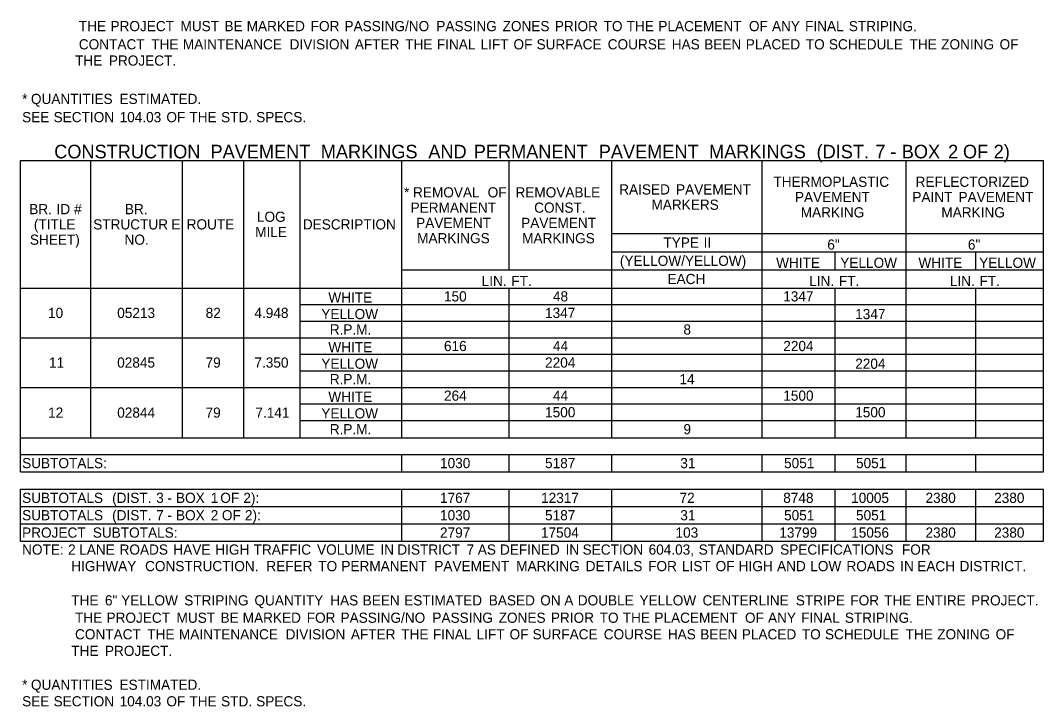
# Model space of a CAD drawing. Extents: x 544478 to 1930787, y -1948294 to 596640.
# Drawn here: x 557631 to 558234, y -1946952 to -1946548 of the extents above; entities that cross this region are included whole.
import ezdxf

# ---------------------------------------------------------------- set-up
doc = ezdxf.new("R2010")
doc.units = 0
doc.layers.add('Default', color=7, linetype='Continuous')

msp = doc.modelspace()

# ---------------------------------------------------------------- linework, layer by layer
at = {"layer": 'Default'}
for p, q in [((557631.45, -1946630.7), (558234.48, -1946630.7)), ((557631.45, -1946630.7), (557856.18, -1946630.7)), ((557631.45, -1946814), (557631.45, -1946630.7)), ((557672.88, -1946794.01), (557672.88, -1946630.7)), ((557727, -1946794.01), (557727, -1946630.7)), ((557763.07, -1946794.01), (557763.07, -1946630.7)), ((557796.22, -1946794.01), (557796.22, -1946630.7)), ((557856.18, -1946794.01), (557856.18, -1946630.7)), ((557919.56, -1946630.7), (557980.01, -1946630.7)), ((557919.56, -1946695.05), (557919.56, -1946630.7)), ((557980.01, -1946794.01), (557980.01, -1946630.7)), ((558068.73, -1946794.01), (558068.73, -1946630.7)), ((558153.56, -1946705.77), (558153.56, -1946630.7)), ((558153.56, -1946794.01), (558153.56, -1946630.7)), ((558234.48, -1946814), (558234.48, -1946630.7)), ((557980.01, -1946673.6), (558234.48, -1946673.6)), ((557980.01, -1946684.32), (558234.48, -1946684.32)), ((558111.63, -1946695.05), (558111.63, -1946684.32)), ((558194.51, -1946695.05), (558194.51, -1946684.32)), ((557856.18, -1946695.05), (558234.48, -1946695.05)), ((558068.73, -1946725.27), (558068.73, -1946695.05)), ((557631.45, -1946705.77), (557856.18, -1946705.77)), ((557631.45, -1946705.77), (557796.22, -1946705.77)), ((557796.22, -1946705.77), (558234.48, -1946705.77)), ((557919.56, -1946725.27), (557919.56, -1946705.77)), ((557919.56, -1946794.01), (557919.56, -1946705.77)), ((558111.63, -1946794.01), (558111.63, -1946705.77)), ((558111.63, -1946794.01), (558111.63, -1946705.77)), ((558194.51, -1946794.01), (558194.51, -1946705.77)), ((558194.51, -1946794.01), (558194.51, -1946705.77)), ((557796.22, -1946715.52), (558234.48, -1946715.52)), ((557796.22, -1946794.01), (557796.22, -1946715.52)), ((557856.18, -1946725.27), (557856.18, -1946715.52)), ((557796.22, -1946725.27), (558234.48, -1946725.27)), ((557631.45, -1946735.02), (558234.48, -1946735.02)), ((557796.22, -1946735.02), (557856.18, -1946735.02)), ((557856.18, -1946754.52), (557856.18, -1946735.02)), ((557919.56, -1946754.52), (557919.56, -1946735.02)), ((558068.73, -1946754.52), (558068.73, -1946735.02)), ((557796.22, -1946744.77), (558234.48, -1946744.77)), ((557796.22, -1946754.52), (558234.48, -1946754.52)), ((557631.45, -1946764.27), (558234.48, -1946764.27)), ((557856.18, -1946783.77), (557856.18, -1946764.27)), ((557919.56, -1946783.77), (557919.56, -1946764.27)), ((558068.73, -1946794.01), (558068.73, -1946764.27)), ((557796.22, -1946774.02), (558234.48, -1946774.02)), ((557796.22, -1946783.77), (558234.48, -1946783.77)), ((557631.45, -1946794.01), (558234.48, -1946794.01)), ((557919.56, -1946794.01), (557980.01, -1946794.01)), ((557980.01, -1946794.01), (558234.48, -1946794.01)), ((557631.45, -1946803.76), (558068.73, -1946803.76)), ((557631.45, -1946803.76), (557980.01, -1946803.76)), ((557856.18, -1946814), (557856.18, -1946803.76)), ((557856.18, -1946814), (557856.18, -1946803.76)), ((557919.56, -1946814), (557919.56, -1946803.76)), ((557919.56, -1946814), (557919.56, -1946803.76)), ((557980.01, -1946803.76), (558234.48, -1946803.76)), ((557980.01, -1946814), (557980.01, -1946803.76)), ((557980.01, -1946814), (557980.01, -1946803.76)), ((558068.73, -1946814), (558068.73, -1946803.76)), ((558068.73, -1946814), (558068.73, -1946803.76)), ((558111.63, -1946803.76), (558234.48, -1946803.76)), ((558111.63, -1946814), (558111.63, -1946803.76)), ((558111.63, -1946814), (558111.63, -1946803.76)), ((558153.56, -1946814), (558153.56, -1946803.76)), ((558153.56, -1946814), (558153.56, -1946803.76)), ((558194.51, -1946814), (558194.51, -1946803.76)), ((558194.51, -1946814), (558194.51, -1946803.76)), ((557631.45, -1946814), (558234.48, -1946814)), ((557631.45, -1946824.24), (558234.48, -1946824.24)), ((557631.45, -1946824.24), (558234.48, -1946824.24)), ((557631.45, -1946854.95), (557631.45, -1946824.24)), ((557856.18, -1946854.95), (557856.18, -1946824.24)), ((557856.18, -1946854.95), (557856.18, -1946824.24)), ((557919.56, -1946854.95), (557919.56, -1946824.24)), ((557919.56, -1946854.95), (557919.56, -1946824.24)), ((557980.01, -1946854.95), (557980.01, -1946824.24)), ((557980.01, -1946854.95), (557980.01, -1946824.24)), ((558068.73, -1946854.95), (558068.73, -1946824.24)), ((558068.73, -1946854.95), (558068.73, -1946824.24)), ((558111.63, -1946854.95), (558111.63, -1946824.24)), ((558111.63, -1946854.95), (558111.63, -1946824.24)), ((558153.56, -1946854.95), (558153.56, -1946824.24)), ((558153.56, -1946854.95), (558153.56, -1946824.24)), ((558194.51, -1946854.95), (558194.51, -1946824.24)), ((558194.51, -1946854.95), (558194.51, -1946824.24)), ((558234.48, -1946854.95), (558234.48, -1946824.24)), ((557631.45, -1946834.47), (558234.48, -1946834.47)), ((557631.45, -1946844.71), (558234.48, -1946844.71)), ((557631.45, -1946854.95), (558234.48, -1946854.95))]:
    msp.add_line(p, q, dxfattribs=at)

# ---------------------------------------------------------------- texts
for s, height, p in [(' THE', 6, (557663.62, -1946554.42)), (' PROJECT', 6, (557682.27, -1946554.42)), (' MUST', 6, (557723.56, -1946554.42)), (' BE', 6, (557749.47, -1946554.42)), (' MARKED', 6, (557762.54, -1946554.42)), (' FOR', 6, (557800.29, -1946554.42)), (' PASSING/NO', 6, (557820.2, -1946554.42)), (' PASSING', 6, (557874.34, -1946554.42)), (' ZONES', 6, (557913.41, -1946554.42)), (' PRIOR', 6, (557944.19, -1946554.42)), (' TO', 6, (557972.95, -1946554.42)), (' THE', 6, (557986.55, -1946554.42)), (' PLACEMENT', 6, (558005.2, -1946554.42)), (' OF', 6, (558058.6, -1946554.42)), (' ANY', 6, (558072.19, -1946554.42)), (' FINAL', 6, (558091.69, -1946554.42)), (' STRIPING.', 6, (558117.48, -1946554.42)), (' CONTACT', 6, (557663.62, -1946565.15)), (' THE', 6, (557706.3, -1946565.15)), (' MAINTENANCE', 6, (557724.95, -1946565.15)), (' DIVISION', 6, (557787.86, -1946565.15)), (' AFTER', 6, (557826.3, -1946565.15)), (' THE', 6, (557856, -1946565.15)), (' FINAL', 6, (557874.65, -1946565.15)), (' LIFT', 6, (557900.43, -1946565.15)), (' OF', 6, (557919.82, -1946565.15)), (' SURFACE', 6, (557933.41, -1946565.15)), (' COURSE', 6, (557975.36, -1946565.15)), (' HAS', 6, (558013.11, -1946565.15)), (' BEEN', 6, (558032.24, -1946565.15)), (' PLACED', 6, (558056.71, -1946565.15)), (' TO', 6, (558092.14, -1946565.15)), (' SCHEDULE', 6, (558105.74, -1946565.15)), (' THE', 6, (558153.28, -1946565.15)), (' ZONING', 6, (558171.93, -1946565.15)), (' OF', 6, (558206.33, -1946565.15)), ('              THE', 6, (557632.42, -1946574.71)), (' PROJECT.', 6, (557681.33, -1946574.71)), ('*', 6, (557632.42, -1946597.32)), (' QUANTITIES', 6, (557635.39, -1946597.32)), (' ESTIMATED.', 6, (557687.59, -1946597.32)), ('SEE', 6, (557632.42, -1946608.05)), (' SECTION', 6, (557648.75, -1946608.05)), (' 104.03', 6, (557687.66, -1946608.05)), (' OF', 6, (557715.24, -1946608.05)), (' THE', 6, (557728.82, -1946608.05)), (' STD.', 6, (557747.47, -1946608.05)), (' SPECS.', 6, (557768.17, -1946608.05)), ('CONSTRUCTION', 8, (557651.35, -1946629.34)), (' PAVEMENT', 8, (557740.5, -1946629.34)), (' MARKINGS', 8, (557805.49, -1946629.34)), (' AND', 8, (557868.9, -1946629.34)), (' PERMANENT', 8, (557895.67, -1946629.34)), (' PAVEMENT', 8, (557969.35, -1946629.34)), (' MARKINGS', 8, (558034.34, -1946629.34)), (' (DIST.', 8, (558097.75, -1946629.34)), (' 7', 8, (558132.37, -1946629.34)), (' BOX', 8, (558147.94, -1946629.34)), (' 2', 8, (558175.26, -1946629.34)), (' OF', 8, (558184.01, -1946629.34)), (' 2)', 8, (558202.12, -1946629.34)), (' -', 8, (558141.2, -1946629.34)), ('THERMOPLASTIC', 6, (558075.26, -1946646.15)), ('REFLECTORIZED', 6, (558159.06, -1946646.15)), ('*', 6, (557857.54, -1946652.37)), (' REMOVAL', 6, (557860.62, -1946652.37)), (' OF', 6, (557904.62, -1946652.37)), ('REMOVABLE', 6, (557923.21, -1946652.37)), ('RAISED', 6, (557984.37, -1946650.65)), (' PAVEMENT', 6, (558015.63, -1946650.65)), ('PAVEMENT', 6, (558087.94, -1946655.15)), ('PAINT', 6, (558157.16, -1946655.15)), (' PAVEMENT', 6, (558182.14, -1946655.15)), ('BR.', 6, (557636.64, -1946662.24)), (' ID', 6, (557650.5, -1946662.24)), (' #', 6, (557660.8, -1946662.24)), ('BR.', 6, (557693.01, -1946662.24)), ('PERMANENT', 6, (557861.41, -1946661.37)), ('CONST.', 6, (557934.24, -1946661.37)), ('MARKERS', 6, (558003.38, -1946659.65)), ('MARKING', 6, (558091.37, -1946664.15)), ('MARKING', 6, (558174.25, -1946664.15)), ('(TITLE', 6, (557639.34, -1946671.24)), ('STRUCTUR', 6, (557674.32, -1946671.24)), ('E', 6, (557720.39, -1946671.24)), ('ROUTE', 6, (557729.41, -1946671.24)), ('LOG', 6, (557770.82, -1946666.74)), ('DESCRIPTION', 6, (557797.89, -1946671.24)), ('PAVEMENT', 6, (557864.67, -1946670.37)), ('PAVEMENT', 6, (557926.58, -1946670.37)), ('MILE', 6, (557769.84, -1946675.74)), ('SHEET)', 6, (557637.01, -1946680.24)), ('NO.', 6, (557692.78, -1946680.24)), ('MARKINGS', 6, (557865.26, -1946679.37)), ('MARKINGS', 6, (557927.17, -1946679.37)), ('TYPE', 6, (558010.41, -1946681.96)), (' II', 6, (558031.89, -1946681.96)), ('6"', 6, (558107.04, -1946683.12)), ('6"', 6, (558189.91, -1946683.12)), ('(YELLOW/YELLOW)', 6, (557984.77, -1946692.69)), ('WHITE', 6, (558076.89, -1946693.85)), ('YELLOW', 6, (558114.67, -1946693.85)), ('WHITE', 6, (558160.74, -1946693.85)), ('YELLOW', 6, (558196.57, -1946693.85)), ('LIN.', 6, (557903.31, -1946704.57)), (' FT.', 6, (557918.56, -1946704.57)), ('EACH', 6, (558012.82, -1946703.41)), ('LIN.', 6, (558096.36, -1946704.57)), (' FT.', 6, (558111.61, -1946704.57)), ('LIN.', 6, (558179.23, -1946704.57)), (' FT.', 6, (558194.49, -1946704.57)), ('150', 6, (557881.08, -1946713.65)), ('48', 6, (557945.31, -1946713.65)), ('1347', 6, (558081.05, -1946713.65)), ('WHITE', 6, (557812.92, -1946714.32)), ('10', 6, (557647.71, -1946723.4)), ('05213', 6, (557688.48, -1946723.4)), ('82', 6, (557740.6, -1946723.4)), ('4.948', 6, (557769.35, -1946723.4)), ('YELLOW', 6, (557808.78, -1946724.07)), ('1347', 6, (557940.65, -1946723.4)), ('1347', 6, (558123.47, -1946724.07)), ('R.P.M.', 6, (557813.76, -1946733.15)), ('8', 6, (558022.23, -1946733.15)), ('WHITE', 6, (557812.92, -1946743.57)), ('616', 6, (557881.07, -1946742.9)), ('44', 6, (557945.33, -1946742.9)), ('2204', 6, (558081.07, -1946742.9)), ('11', 6, (557648.28, -1946752.65)), ('02845', 6, (557688.46, -1946752.65)), ('79', 6, (557740.56, -1946752.65)), ('7.350', 6, (557769.36, -1946752.65)), ('YELLOW', 6, (557808.78, -1946753.32)), ('2204', 6, (557940.67, -1946752.65)), ('2204', 6, (558123.48, -1946753.32)), ('R.P.M.', 6, (557813.76, -1946762.4)), ('14', 6, (558019.92, -1946762.4)), ('WHITE', 6, (557812.92, -1946772.82)), ('264', 6, (557881.09, -1946772.15)), ('44', 6, (557945.33, -1946772.15)), ('1500', 6, (558081.07, -1946772.15)), ('12', 6, (557647.73, -1946782.14)), ('02844', 6, (557688.49, -1946782.14)), ('79', 6, (557740.56, -1946782.14)), ('7.141', 6, (557769.93, -1946782.14)), ('YELLOW', 6, (557808.78, -1946782.57)), ('1500', 6, (557940.67, -1946781.9)), ('1500', 6, (558123.48, -1946781.9)), ('R.P.M.', 6, (557813.76, -1946791.89)), ('9', 6, (558022.23, -1946791.89)), ('SUBTOTALS:', 6, (557632.42, -1946811.88)), ('1030', 6, (557878.76, -1946811.88)), ('5187', 6, (557940.65, -1946811.88)), ('31', 6, (558020.39, -1946811.88)), ('5051', 6, (558081.54, -1946811.88)), ('5051', 6, (558123.96, -1946811.88)), ('SUBTOTALS', 6, (557632.42, -1946832.36)), (' (DIST.', 6, (557683.25, -1946832.36)), (' 3', 6, (557709.21, -1946832.36)), (' BOX', 6, (557720.9, -1946832.36)), (' 1', 6, (557741.39, -1946832.36)), (' OF', 6, (557747.02, -1946832.36)), (' 2):', 6, (557760.6, -1946832.36)), ('1767', 6, (557878.74, -1946832.36)), ('12317', 6, (557938.32, -1946832.36)), ('72', 6, (558019.92, -1946832.36)), ('8748', 6, (558081.05, -1946832.36)), ('10005', 6, (558121.07, -1946832.36)), ('2380', 6, (558164.92, -1946832.36)), ('2380', 6, (558205.38, -1946832.36)), (' -', 6, (557715.84, -1946832.36)), ('SUBTOTALS', 6, (557632.42, -1946842.59)), (' (DIST.', 6, (557683.25, -1946842.59)), (' 7', 6, (557709.21, -1946842.59)), (' -', 6, (557715.83, -1946842.59)), (' BOX', 6, (557720.89, -1946842.59)), (' 2', 6, (557741.38, -1946842.59)), (' OF', 6, (557747.94, -1946842.59)), (' 2):', 6, (557761.53, -1946842.59)), ('1030', 6, (557878.76, -1946842.59)), ('5187', 6, (557940.65, -1946842.59)), ('31', 6, (558020.39, -1946842.59)), ('5051', 6, (558081.54, -1946842.59)), ('5051', 6, (558123.96, -1946842.59)), ('PROJECT', 6, (557632.42, -1946852.83)), (' SUBTOTALS:', 6, (557671.85, -1946852.83)), ('2797', 6, (557878.74, -1946852.83)), ('17504', 6, (557938.23, -1946852.83)), ('103', 6, (558017.56, -1946852.83)), ('13799', 6, (558078.73, -1946852.83)), ('15056', 6, (558121.1, -1946852.83)), ('2380', 6, (558164.92, -1946852.83)), ('2380', 6, (558205.38, -1946852.83)), ('NOTE:', 6, (557632.42, -1946862.82)), (' 2', 6, (557657.31, -1946862.82)), (' LANE', 6, (557663.85, -1946862.82)), (' ROADS', 6, (557687.63, -1946862.82)), (' HAVE', 6, (557719.34, -1946862.82)), (' HIGH', 6, (557744.05, -1946862.82)), (' TRAFFIC', 6, (557766.66, -1946862.82)), (' VOLUME', 6, (557804.05, -1946862.82)), (' IN', 6, (557841.34, -1946862.82)), (' DISTRICT', 6, (557851.36, -1946862.82)), (' 7', 6, (557892.18, -1946862.82)), (' AS', 6, (557898.79, -1946862.82)), (' DEFINED', 6, (557911.86, -1946862.82)), (' IN', 6, (557950.54, -1946862.82)), (' SECTION', 6, (557960.57, -1946862.82)), (' 604.03,', 6, (557999.47, -1946862.82)), (' STANDARD', 6, (558029.01, -1946862.82)), (' SPECIFICATIONS', 6, (558077.01, -1946862.82)), (' FOR', 6, (558148.78, -1946862.82)), ('             HIGHWAY', 6, (557632.42, -1946872.57)), (' CONSTRUCTION.', 6, (557702.67, -1946872.57)), (' REFER', 6, (557774.14, -1946872.57)), (' TO', 6, (557804.77, -1946872.57)), (' PERMANENT', 6, (557818.36, -1946872.57)), (' PAVEMENT', 6, (557873.16, -1946872.57)), (' MARKING', 6, (557921.45, -1946872.57)), (' DETAILS', 6, (557962.38, -1946872.57)), (' FOR', 6, (557999.21, -1946872.57)), (' LIST', 6, (558019.12, -1946872.57)), (' OF', 6, (558038.98, -1946872.57)), (' HIGH', 6, (558052.57, -1946872.57)), (' AND', 6, (558075.18, -1946872.57)), (' LOW', 6, (558094.76, -1946872.57)), (' ROADS', 6, (558116.08, -1946872.57)), (' IN', 6, (558147.79, -1946872.57)), (' EACH', 6, (558157.82, -1946872.57)), (' DISTRICT.', 6, (558182.76, -1946872.57)), ('             THE', 6, (557632.42, -1946892.75)), (' 6"', 6, (557679, -1946892.75)), (' YELLOW', 6, (557688.58, -1946892.75)), (' STRIPING', 6, (557725.75, -1946892.75)), (' QUANTITY', 6, (557767.14, -1946892.75)), (' HAS', 6, (557811.8, -1946892.75)), (' BEEN', 6, (557830.92, -1946892.75)), (' ESTIMATED', 6, (557855.4, -1946892.75)), (' BASED', 6, (557905.26, -1946892.75)), (' ON', 6, (557935.57, -1946892.75)), (' A', 6, (557949.79, -1946892.75)), (' DOUBLE', 6, (557957.72, -1946892.75)), (' YELLOW', 6, (557994.08, -1946892.75)), (' CENTERLINE', 6, (558031.25, -1946892.75)), (' STRIPE', 6, (558086.24, -1946892.75)), (' FOR', 6, (558118.4, -1946892.75)), (' THE', 6, (558138.31, -1946892.75)), (' ENTIRE', 6, (558156.96, -1946892.75)), (' PROJECT.', 6, (558189.58, -1946892.75)), ('THE', 6, (557663.62, -1946902.99)), (' PROJECT', 6, (557679.94, -1946902.99)), (' MUST', 6, (557721.23, -1946902.99)), (' BE', 6, (557747.15, -1946902.99)), (' MARKED', 6, (557760.21, -1946902.99)), (' FOR', 6, (557797.96, -1946902.99)), (' PASSING/NO', 6, (557817.87, -1946902.99)), (' PASSING', 6, (557872.01, -1946902.99)), (' ZONES', 6, (557911.09, -1946902.99)), (' PRIOR', 6, (557941.86, -1946902.99)), (' TO', 6, (557970.62, -1946902.99)), (' THE', 6, (557984.22, -1946902.99)), (' PLACEMENT', 6, (558002.87, -1946902.99)), (' OF', 6, (558056.27, -1946902.99)), (' ANY', 6, (558069.86, -1946902.99)), (' FINAL', 6, (558089.37, -1946902.99)), (' STRIPING.', 6, (558115.15, -1946902.99)), ('CONTACT', 6, (557663.62, -1946912.74)), (' THE', 6, (557703.98, -1946912.74)), (' MAINTENANCE', 6, (557722.62, -1946912.74)), (' DIVISION', 6, (557785.53, -1946912.74)), (' AFTER', 6, (557823.97, -1946912.74)), (' THE', 6, (557853.67, -1946912.74)), (' FINAL', 6, (557872.32, -1946912.74)), (' LIFT', 6, (557898.11, -1946912.74)), (' OF', 6, (557917.5, -1946912.74)), (' SURFACE', 6, (557931.08, -1946912.74)), (' COURSE', 6, (557973.03, -1946912.74)), (' HAS', 6, (558010.78, -1946912.74)), (' BEEN', 6, (558029.91, -1946912.74)), (' PLACED', 6, (558054.39, -1946912.74)), (' TO', 6, (558089.81, -1946912.74)), (' SCHEDULE', 6, (558103.41, -1946912.74)), (' THE', 6, (558150.95, -1946912.74)), (' ZONING', 6, (558169.6, -1946912.74)), (' OF', 6, (558204, -1946912.74)), ('             THE', 6, (557632.42, -1946922.49)), (' PROJECT.', 6, (557679, -1946922.49)), ('*', 6, (557632.42, -1946942.47)), (' QUANTITIES', 6, (557635.39, -1946942.47)), (' ESTIMATED.', 6, (557687.59, -1946942.47)), ('SEE', 6, (557632.42, -1946952.22)), (' SECTION', 6, (557648.75, -1946952.22)), (' 104.03', 6, (557687.66, -1946952.22)), (' OF', 6, (557715.24, -1946952.22)), (' THE', 6, (557728.82, -1946952.22)), (' STD.', 6, (557747.47, -1946952.22)), (' SPECS.', 6, (557768.17, -1946952.22))]:
    msp.add_text(s, height=height, dxfattribs=at).set_placement(p)

doc.saveas('drawing.dxf')
